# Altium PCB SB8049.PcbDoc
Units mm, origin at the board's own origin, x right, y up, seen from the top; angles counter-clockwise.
Board outline 80 x 49 mm, 2 copper layers (Top Layer, Bottom Layer); 0 components, 0 nets, 4 pads, 0 vias.
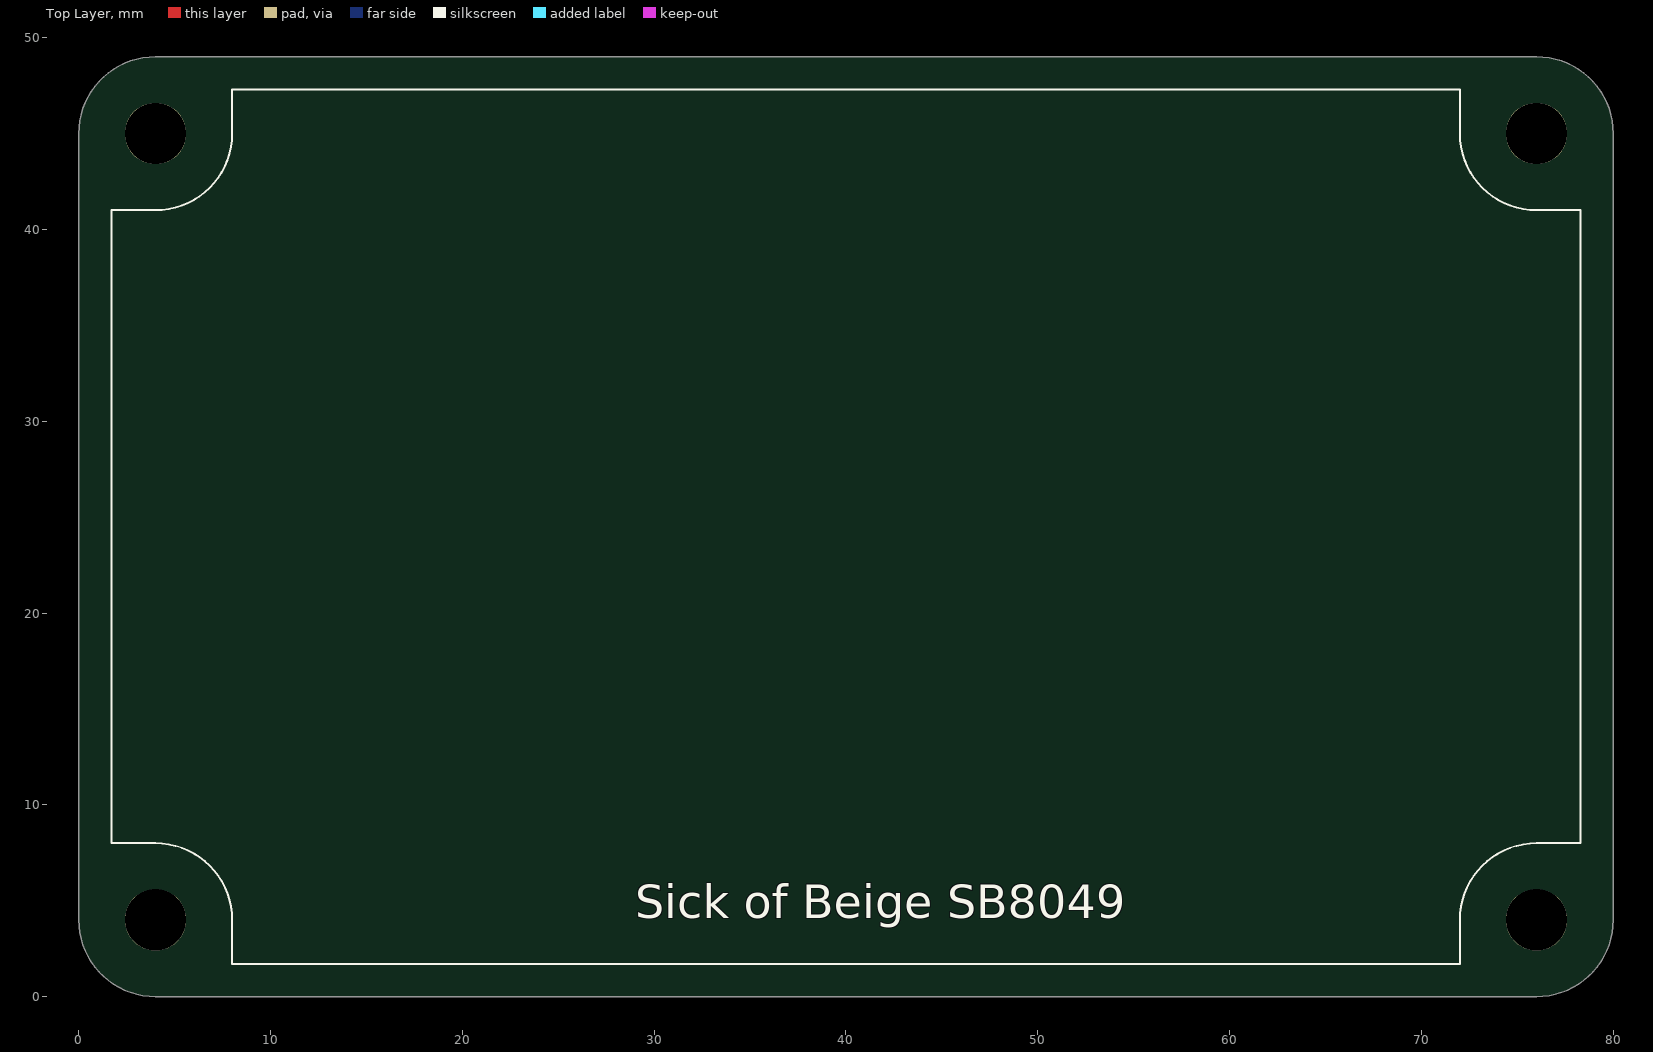
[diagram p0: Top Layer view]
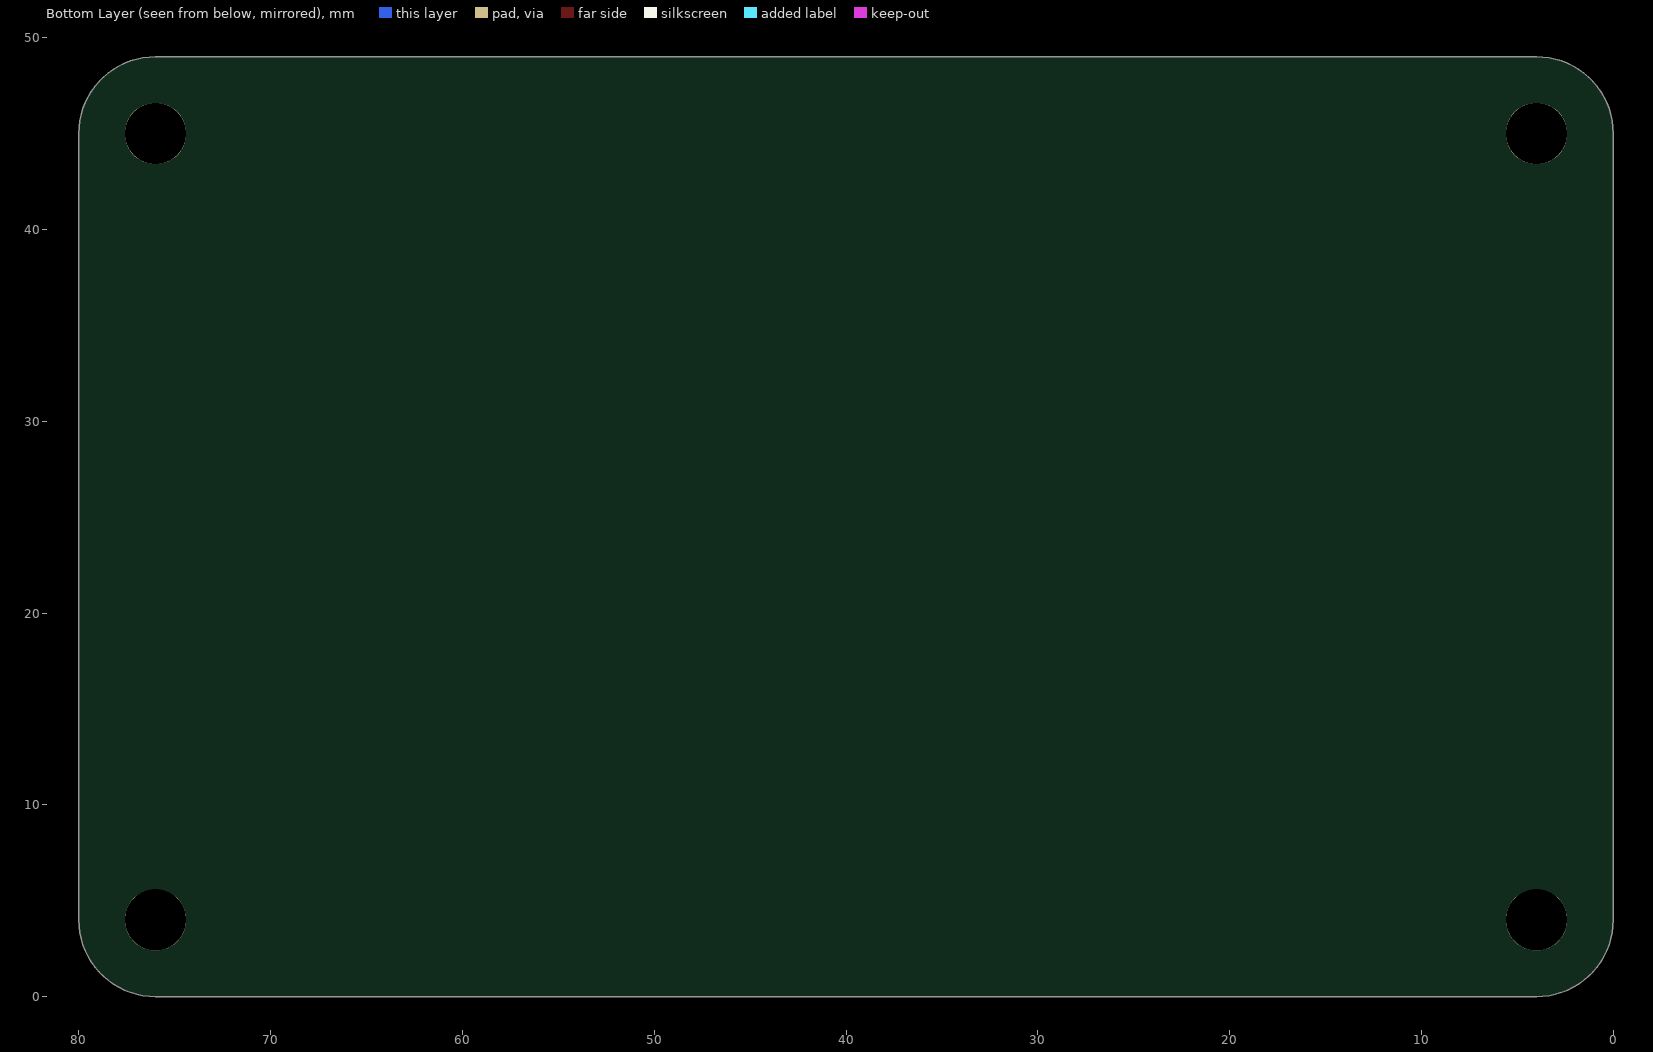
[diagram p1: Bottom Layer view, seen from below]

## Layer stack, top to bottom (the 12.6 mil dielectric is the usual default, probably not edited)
Top Layer: signal copper 0.0356
Dielectric: dielectric 0.32, FR-4, Dk 4.8
Bottom Layer: signal copper 0.0356

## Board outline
0,4 0,45 cw(c4,45) 4,49 76,49 cw(c76,45) 80,45 80,4 cw(c76,4) 76,0 4,0 cw(c4,4)

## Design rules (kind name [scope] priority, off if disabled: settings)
Clearance [All] p1: gap=0.254
PolygonConnect [All] p1: connectstyle=Relief reliefconductorwidth=0.254 reliefentries=4 polygonreliefangle="90 Angle" airgapwidth=0.254
RoutingVias [All] p1: holewidth=0.711 width=1.27 viastyle="Through Hole" minholewidth=0.711 minwidth=1.27 maxholewidth=0.711 maxwidth=1.27
SolderMaskExpansion [All] p1: expansion=0.102
Width [All] p1: maxlimit=0.254 minlimit=0.254 preferedwidth=0.254
28 further rules are at their usual default settings.

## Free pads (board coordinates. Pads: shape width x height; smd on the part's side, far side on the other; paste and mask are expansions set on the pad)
  round 3.2 hole 3.2 unplated: 0(4,4) 1(4,45) 2(76,45) 3(76,4)

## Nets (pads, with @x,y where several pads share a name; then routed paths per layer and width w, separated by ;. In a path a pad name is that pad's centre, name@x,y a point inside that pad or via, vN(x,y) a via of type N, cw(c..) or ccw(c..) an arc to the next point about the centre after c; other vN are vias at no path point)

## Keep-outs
Top Overlay:
  lines w0.102: 1.7,8 4,8 cw(c4,4) 8,4 8,1.7 72,1.7 72,4 cw(c76,4) 76,8 78.3,8 78.3,41 76,41 cw(c76,45) 72,45 72,47.3 8,47.3 8,45 cw(c4,45) 4,41 1.7,41 1.7,8

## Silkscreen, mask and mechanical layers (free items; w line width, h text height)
Top Overlay:
  text "Sick of Beige SB8049" at 29,3.5 h3
Mechanical 1:
  the board outline again, w0.102
Mechanical 4:
  circle w0.102: c76,4 r1.6
  circle w0.102: c4,4 r1.6
  circle w0.102: c4,45 r1.6
  circle w0.102: c76,45 r1.6
  lines w0.102: 0,24.5 80,24.5 ; 40,0 40,49

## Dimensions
76,49 to 76,0 on Mechanical 3
0,4 to 80,4 on Mechanical 3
